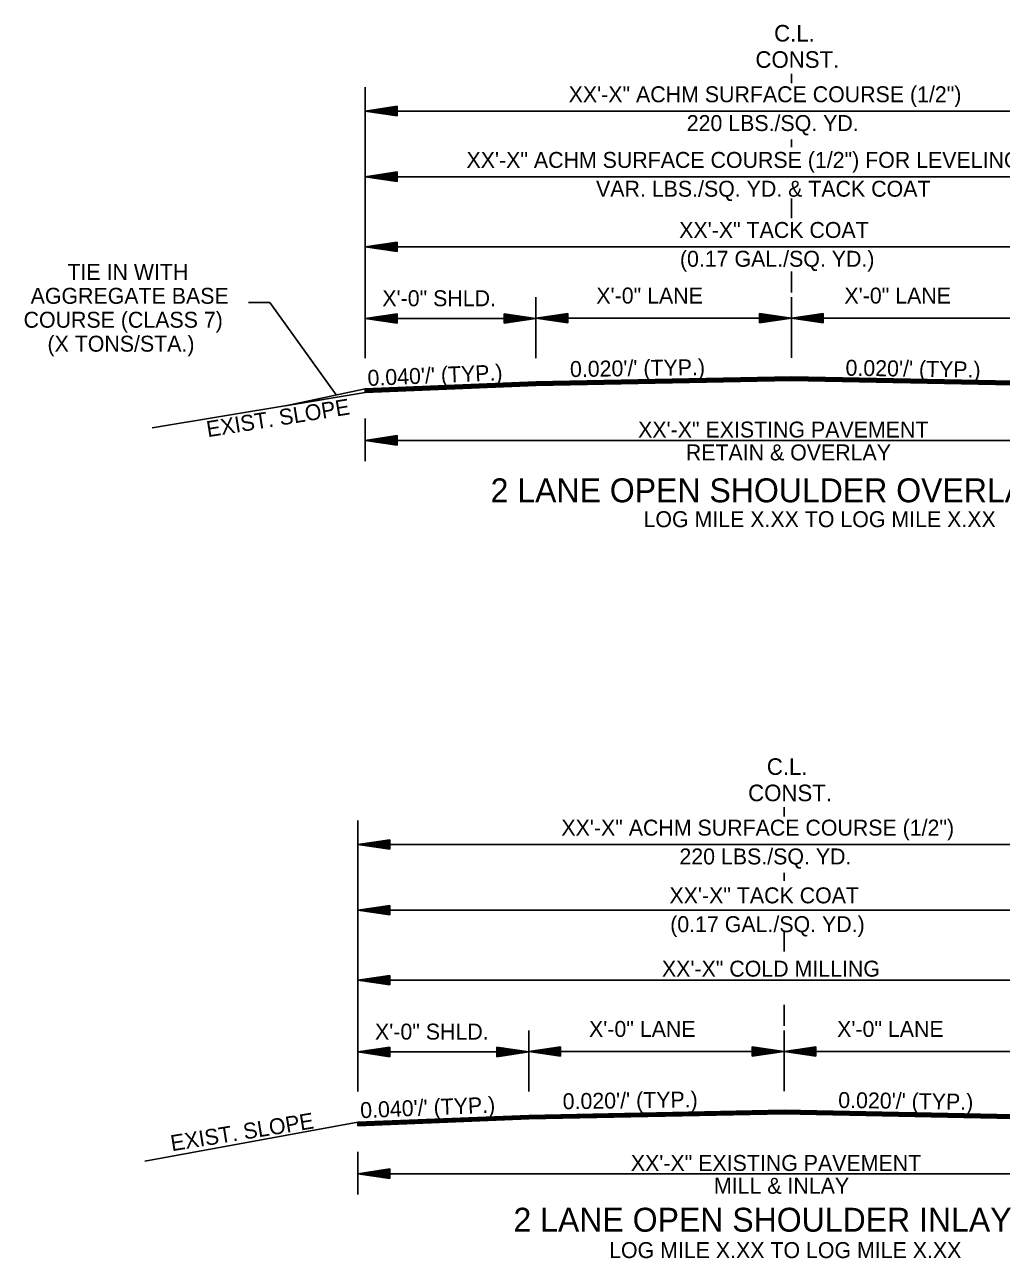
# Model space of a CAD drawing. Extents: x 542112 to 1930787, y -1968972 to 596640.
# Drawn here: x 546620 to 547079, y -1954575 to -1953995 of the extents above; entities that cross this region are included whole.
import ezdxf

# ---------------------------------------------------------------- set-up
doc = ezdxf.new("R2010")
doc.units = 0
doc.layers.add('R_Draft', color=7, linetype='Continuous')

msp = doc.modelspace()

# ---------------------------------------------------------------- linework, layer by layer
at = {"layer": 'R_Draft'}
for p, q in [((546980.34, -1954022.43), (546980.34, -1954018.02)), ((546780.08, -1954024.27), (546780.08, -1954151.7)), ((546795.08, -1954033.28), (546780.08, -1954035.53)), ((546780.08, -1954035.53), (547180.53, -1954035.53)), ((546795.08, -1954037.78), (546780.08, -1954035.53)), ((546795.08, -1954033.66), (546782.59, -1954035.53)), ((546795.08, -1954037.41), (546782.59, -1954035.53)), ((546795.08, -1954034.04), (546785.17, -1954035.53)), ((546795.08, -1954037.03), (546785.17, -1954035.53)), ((546795.08, -1954034.42), (546787.66, -1954035.53)), ((546795.08, -1954036.65), (546787.66, -1954035.53)), ((546795.08, -1954034.8), (546790.21, -1954035.53)), ((546795.08, -1954036.26), (546790.21, -1954035.53)), ((546795.08, -1954035.18), (546792.71, -1954035.53)), ((546795.08, -1954035.89), (546792.71, -1954035.53)), ((546795.08, -1954037.78), (546795.08, -1954033.28)), ((546980.34, -1954052.56), (546980.34, -1954048.89)), ((546795.08, -1954064.15), (546780.08, -1954066.4)), ((546795.08, -1954064.53), (546782.59, -1954066.4)), ((546795.08, -1954064.91), (546785.17, -1954066.4)), ((546795.08, -1954065.29), (546787.66, -1954066.4)), ((546795.08, -1954068.65), (546795.08, -1954064.15)), ((546780.08, -1954066.4), (547180.53, -1954066.4)), ((546795.08, -1954068.65), (546780.08, -1954066.4)), ((546795.08, -1954068.28), (546782.59, -1954066.4)), ((546795.08, -1954067.9), (546785.17, -1954066.4)), ((546795.08, -1954067.52), (546787.66, -1954066.4)), ((546795.08, -1954065.67), (546790.21, -1954066.4)), ((546795.08, -1954067.13), (546790.21, -1954066.4)), ((546795.08, -1954066.05), (546792.71, -1954066.4)), ((546795.08, -1954066.76), (546792.71, -1954066.4)), ((546980.34, -1954085.92), (546980.34, -1954076.62)), ((546795.08, -1954097.08), (546780.08, -1954099.33)), ((546780.08, -1954099.33), (547180.53, -1954099.33)), ((546795.08, -1954101.58), (546780.08, -1954099.33)), ((546795.08, -1954097.46), (546782.59, -1954099.33)), ((546795.08, -1954101.21), (546782.59, -1954099.33)), ((546795.08, -1954097.84), (546785.17, -1954099.33)), ((546795.08, -1954100.83), (546785.17, -1954099.33)), ((546795.08, -1954098.22), (546787.66, -1954099.33)), ((546795.08, -1954100.45), (546787.66, -1954099.33)), ((546795.08, -1954098.6), (546790.21, -1954099.33)), ((546795.08, -1954100.06), (546790.21, -1954099.33)), ((546795.08, -1954098.98), (546792.71, -1954099.33)), ((546795.08, -1954099.69), (546792.71, -1954099.33)), ((546795.08, -1954101.58), (546795.08, -1954097.08)), ((546980.34, -1954120.86), (546980.34, -1954110.99)), ((546860.34, -1954151.53), (546860.34, -1954122.98)), ((546860.34, -1954151.7), (546860.34, -1954122.98)), ((546980.34, -1954151.53), (546980.34, -1954122.98)), ((546795.08, -1954130.79), (546780.08, -1954133.04)), ((546860.34, -1954133.04), (546780.08, -1954133.04)), ((546795.08, -1954135.29), (546780.08, -1954133.04)), ((546795.08, -1954131.17), (546782.59, -1954133.04)), ((546795.08, -1954134.92), (546782.59, -1954133.04)), ((546795.08, -1954131.55), (546785.17, -1954133.04)), ((546795.08, -1954134.53), (546785.17, -1954133.04)), ((546795.08, -1954131.92), (546787.66, -1954133.04)), ((546795.08, -1954134.16), (546787.66, -1954133.04)), ((546795.08, -1954132.31), (546790.21, -1954133.04)), ((546795.08, -1954133.77), (546790.21, -1954133.04)), ((546795.08, -1954132.69), (546792.71, -1954133.04)), ((546795.08, -1954133.39), (546792.71, -1954133.04)), ((546795.08, -1954135.29), (546795.08, -1954130.79)), ((546845.34, -1954130.79), (546860.34, -1954133.04)), ((546845.34, -1954130.79), (546845.34, -1954135.29)), ((546845.34, -1954131.17), (546857.84, -1954133.04)), ((546845.34, -1954131.55), (546855.26, -1954133.04)), ((546845.34, -1954131.92), (546852.76, -1954133.04)), ((546845.34, -1954132.31), (546850.22, -1954133.04)), ((546845.34, -1954132.69), (546847.71, -1954133.04)), ((546845.34, -1954135.29), (546860.34, -1954133.04)), ((546845.34, -1954133.78), (546850.22, -1954133.04)), ((546845.34, -1954134.53), (546855.26, -1954133.04)), ((546845.34, -1954134.92), (546857.84, -1954133.04)), ((546845.34, -1954134.16), (546852.76, -1954133.04)), ((546845.34, -1954133.39), (546847.71, -1954133.04)), ((546875.34, -1954130.62), (546860.34, -1954132.87)), ((546980.34, -1954132.87), (546860.34, -1954132.87)), ((546875.34, -1954135.12), (546860.34, -1954132.87)), ((546875.34, -1954131), (546862.85, -1954132.87)), ((546875.34, -1954134.75), (546862.85, -1954132.87)), ((546875.34, -1954131.38), (546865.43, -1954132.87)), ((546875.34, -1954134.36), (546865.43, -1954132.87)), ((546875.34, -1954131.75), (546867.93, -1954132.87)), ((546875.34, -1954133.99), (546867.93, -1954132.87)), ((546875.34, -1954132.14), (546870.47, -1954132.87)), ((546875.34, -1954133.6), (546870.47, -1954132.87)), ((546875.34, -1954132.52), (546872.97, -1954132.87)), ((546875.34, -1954133.22), (546872.97, -1954132.87)), ((546875.34, -1954135.12), (546875.34, -1954130.62)), ((546965.34, -1954130.62), (546980.34, -1954132.87)), ((546965.34, -1954130.62), (546965.34, -1954135.12)), ((546965.34, -1954131), (546977.84, -1954132.87)), ((546965.34, -1954131.38), (546975.26, -1954132.87)), ((546965.34, -1954131.75), (546972.76, -1954132.87)), ((546965.34, -1954132.14), (546970.22, -1954132.87)), ((546965.34, -1954132.52), (546967.71, -1954132.87)), ((546965.34, -1954135.12), (546980.34, -1954132.87)), ((546965.34, -1954133.61), (546970.22, -1954132.87)), ((546965.34, -1954134.36), (546975.26, -1954132.87)), ((546965.34, -1954134.75), (546977.84, -1954132.87)), ((546965.34, -1954133.99), (546972.76, -1954132.87)), ((546965.34, -1954133.22), (546967.71, -1954132.87)), ((546995.34, -1954130.62), (546980.34, -1954132.87)), ((547100.27, -1954132.87), (546980.34, -1954132.87)), ((546995.34, -1954135.12), (546980.34, -1954132.87)), ((546995.34, -1954131), (546982.85, -1954132.87)), ((546995.34, -1954134.75), (546982.85, -1954132.87)), ((546995.34, -1954131.38), (546985.43, -1954132.87)), ((546995.34, -1954134.36), (546985.43, -1954132.87)), ((546995.34, -1954131.75), (546987.93, -1954132.87)), ((546995.34, -1954133.99), (546987.93, -1954132.87)), ((546995.34, -1954132.14), (546990.47, -1954132.87)), ((546995.34, -1954133.6), (546990.47, -1954132.87)), ((546995.34, -1954132.52), (546992.97, -1954132.87)), ((546995.34, -1954133.22), (546992.97, -1954132.87)), ((546995.34, -1954135.12), (546995.34, -1954130.62)), ((546780.08, -1954166.09), (546860.34, -1954162.88)), ((546780.08, -1954166.39), (546860.36, -1954163.18)), ((546780.08, -1954166.69), (546860.37, -1954163.48)), ((546780.08, -1954166.99), (546860.38, -1954163.78)), ((546780.08, -1954167.29), (546860.39, -1954164.08)), ((546980.34, -1954160.48), (546860.34, -1954162.88)), ((546980.35, -1954160.78), (546860.35, -1954163.18)), ((546980.36, -1954161.08), (546860.36, -1954163.48)), ((546980.36, -1954161.38), (546860.36, -1954163.78)), ((546980.37, -1954161.68), (546860.37, -1954164.08)), ((546980.37, -1954161.98), (546860.37, -1954164.38)), ((546980.38, -1954162.18), (546860.38, -1954164.58)), ((546980.31, -1954161.98), (547100.31, -1954164.38)), ((546980.31, -1954162.18), (547100.31, -1954164.58)), ((546980.32, -1954161.68), (547100.32, -1954164.08)), ((546980.33, -1954161.08), (547100.33, -1954163.48)), ((546980.33, -1954161.38), (547100.33, -1954163.78)), ((546980.34, -1954160.48), (547100.34, -1954162.88)), ((546980.34, -1954160.78), (547100.34, -1954163.18)), ((546780.08, -1954167.79), (546680.01, -1954184.46)), ((546780.08, -1954166.09), (546742.59, -1954174.03)), ((546742.59, -1954174.03), (546780.08, -1954167.79)), ((546780.08, -1954167.59), (546860.4, -1954164.38)), ((546780.08, -1954167.79), (546860.41, -1954164.58)), ((546780.08, -1954167.79), (546780.08, -1954166.09)), ((546780.08, -1954167.79), (546780.08, -1954166.09)), ((546780.08, -1954167.79), (546780.08, -1954166.09)), ((546780.08, -1954167.79), (546780.08, -1954167.79)), ((546780.08, -1954180.09), (546780.08, -1954200.09)), ((546795.08, -1954188.09), (546780.08, -1954190.34)), ((546780.08, -1954190.34), (547180.53, -1954190.34)), ((546795.08, -1954192.59), (546780.08, -1954190.34)), ((546795.08, -1954188.46), (546782.59, -1954190.34)), ((546795.08, -1954192.21), (546782.59, -1954190.34)), ((546795.08, -1954188.84), (546785.17, -1954190.34)), ((546795.08, -1954191.83), (546785.17, -1954190.34)), ((546795.08, -1954189.22), (546787.66, -1954190.34)), ((546795.08, -1954191.45), (546787.66, -1954190.34)), ((546795.08, -1954189.6), (546790.21, -1954190.34)), ((546795.08, -1954191.06), (546790.21, -1954190.34)), ((546795.08, -1954189.98), (546792.71, -1954190.34)), ((546795.08, -1954190.69), (546792.71, -1954190.34)), ((546795.08, -1954192.59), (546795.08, -1954188.09)), ((546976.91, -1954367.23), (546976.91, -1954362.81)), ((546776.65, -1954369.07), (546776.65, -1954496.49)), ((546791.65, -1954378.08), (546776.65, -1954380.33)), ((546791.65, -1954378.45), (546779.16, -1954380.33)), ((546791.65, -1954382.58), (546791.65, -1954378.08)), ((546776.65, -1954380.33), (547177.1, -1954380.33)), ((546791.65, -1954382.58), (546776.65, -1954380.33)), ((546791.65, -1954382.2), (546779.16, -1954380.33)), ((546791.65, -1954378.84), (546781.74, -1954380.33)), ((546791.65, -1954381.82), (546781.74, -1954380.33)), ((546791.65, -1954379.21), (546784.24, -1954380.33)), ((546791.65, -1954381.45), (546784.24, -1954380.33)), ((546791.65, -1954379.59), (546786.78, -1954380.33)), ((546791.65, -1954381.06), (546786.78, -1954380.33)), ((546791.65, -1954379.98), (546789.28, -1954380.33)), ((546791.65, -1954380.68), (546789.28, -1954380.33)), ((546976.91, -1954397.35), (546976.91, -1954393.68)), ((546791.65, -1954408.95), (546776.65, -1954411.2)), ((546776.65, -1954411.2), (547177.1, -1954411.2)), ((546791.65, -1954413.45), (546776.65, -1954411.2)), ((546791.65, -1954409.32), (546779.16, -1954411.2)), ((546791.65, -1954413.07), (546779.16, -1954411.2)), ((546791.65, -1954409.71), (546781.74, -1954411.2)), ((546791.65, -1954412.69), (546781.74, -1954411.2)), ((546791.65, -1954410.08), (546784.24, -1954411.2)), ((546791.65, -1954412.32), (546784.24, -1954411.2)), ((546791.65, -1954410.46), (546786.78, -1954411.2)), ((546791.65, -1954411.93), (546786.78, -1954411.2)), ((546791.65, -1954410.85), (546789.28, -1954411.2)), ((546791.65, -1954411.55), (546789.28, -1954411.2)), ((546791.65, -1954413.45), (546791.65, -1954408.95)), ((546976.91, -1954430.71), (546976.91, -1954421.41)), ((546791.65, -1954441.88), (546776.65, -1954444.13)), ((546791.65, -1954442.25), (546779.16, -1954444.13)), ((546791.65, -1954446.38), (546791.65, -1954441.88)), ((546776.65, -1954444.13), (547177.1, -1954444.13)), ((546791.65, -1954446.38), (546776.65, -1954444.13)), ((546791.65, -1954446), (546779.16, -1954444.13)), ((546791.65, -1954442.63), (546781.74, -1954444.13)), ((546791.65, -1954445.62), (546781.74, -1954444.13)), ((546791.65, -1954443.01), (546784.24, -1954444.13)), ((546791.65, -1954445.24), (546784.24, -1954444.13)), ((546791.65, -1954443.39), (546786.78, -1954444.13)), ((546791.65, -1954444.85), (546786.78, -1954444.13)), ((546791.65, -1954443.77), (546789.28, -1954444.13)), ((546791.65, -1954444.48), (546789.28, -1954444.13)), ((546976.91, -1954465.65), (546976.91, -1954455.78)), ((546856.91, -1954496.32), (546856.91, -1954467.77)), ((546856.91, -1954496.49), (546856.91, -1954467.77)), ((546976.91, -1954496.32), (546976.91, -1954467.77)), ((546791.65, -1954475.58), (546776.65, -1954477.83)), ((546791.65, -1954475.96), (546779.16, -1954477.83)), ((546791.65, -1954476.34), (546781.74, -1954477.83)), ((546791.65, -1954476.72), (546784.24, -1954477.83)), ((546791.65, -1954477.1), (546786.78, -1954477.83)), ((546791.65, -1954480.08), (546791.65, -1954475.58)), ((546841.91, -1954475.58), (546856.91, -1954477.83)), ((546841.91, -1954475.58), (546841.91, -1954480.08)), ((546841.91, -1954475.96), (546854.41, -1954477.83)), ((546841.91, -1954476.34), (546851.83, -1954477.83)), ((546841.91, -1954476.72), (546849.33, -1954477.83)), ((546841.91, -1954477.11), (546846.79, -1954477.83)), ((546871.91, -1954475.41), (546856.91, -1954477.66)), ((546871.91, -1954475.79), (546859.42, -1954477.66)), ((546871.91, -1954476.17), (546862, -1954477.66)), ((546871.91, -1954476.55), (546864.5, -1954477.66)), ((546871.91, -1954476.93), (546867.04, -1954477.66)), ((546871.91, -1954477.31), (546869.54, -1954477.66)), ((546871.91, -1954479.91), (546871.91, -1954475.41)), ((546961.91, -1954475.41), (546976.91, -1954477.66)), ((546961.91, -1954475.41), (546961.91, -1954479.91)), ((546961.91, -1954475.79), (546974.41, -1954477.66)), ((546961.91, -1954476.17), (546971.83, -1954477.66)), ((546961.91, -1954476.55), (546969.33, -1954477.66)), ((546961.91, -1954476.94), (546966.79, -1954477.66)), ((546961.91, -1954477.31), (546964.28, -1954477.66)), ((546991.91, -1954475.41), (546976.91, -1954477.66)), ((546991.91, -1954475.79), (546979.42, -1954477.66)), ((546991.91, -1954476.17), (546982, -1954477.66)), ((546991.91, -1954476.55), (546984.5, -1954477.66)), ((546991.91, -1954476.93), (546987.04, -1954477.66)), ((546991.91, -1954477.31), (546989.54, -1954477.66)), ((546991.91, -1954479.91), (546991.91, -1954475.41)), ((546856.91, -1954477.83), (546776.65, -1954477.83)), ((546791.65, -1954480.08), (546776.65, -1954477.83)), ((546791.65, -1954479.71), (546779.16, -1954477.83)), ((546791.65, -1954479.33), (546781.74, -1954477.83)), ((546791.65, -1954478.95), (546784.24, -1954477.83)), ((546791.65, -1954478.56), (546786.78, -1954477.83)), ((546791.65, -1954477.48), (546789.28, -1954477.83)), ((546791.65, -1954478.19), (546789.28, -1954477.83)), ((546841.91, -1954477.48), (546844.28, -1954477.83)), ((546841.91, -1954480.08), (546856.91, -1954477.83)), ((546841.91, -1954478.57), (546846.79, -1954477.83)), ((546841.91, -1954479.33), (546851.83, -1954477.83)), ((546841.91, -1954479.71), (546854.41, -1954477.83)), ((546841.91, -1954478.95), (546849.33, -1954477.83)), ((546841.91, -1954478.19), (546844.28, -1954477.83)), ((546976.91, -1954477.66), (546856.91, -1954477.66)), ((546871.91, -1954479.91), (546856.91, -1954477.66)), ((546871.91, -1954479.54), (546859.42, -1954477.66)), ((546871.91, -1954479.16), (546862, -1954477.66)), ((546871.91, -1954478.78), (546864.5, -1954477.66)), ((546871.91, -1954478.39), (546867.04, -1954477.66)), ((546871.91, -1954478.02), (546869.54, -1954477.66)), ((546961.91, -1954479.91), (546976.91, -1954477.66)), ((546961.91, -1954478.4), (546966.79, -1954477.66)), ((546961.91, -1954479.16), (546971.83, -1954477.66)), ((546961.91, -1954479.54), (546974.41, -1954477.66)), ((546961.91, -1954478.78), (546969.33, -1954477.66)), ((546961.91, -1954478.02), (546964.28, -1954477.66)), ((547096.84, -1954477.66), (546976.91, -1954477.66)), ((546991.91, -1954479.91), (546976.91, -1954477.66)), ((546991.91, -1954479.54), (546979.42, -1954477.66)), ((546991.91, -1954479.16), (546982, -1954477.66)), ((546991.91, -1954478.78), (546984.5, -1954477.66)), ((546991.91, -1954478.39), (546987.04, -1954477.66)), ((546991.91, -1954478.02), (546989.54, -1954477.66)), ((546976.91, -1954505.27), (546856.91, -1954507.67)), ((546976.92, -1954505.57), (546856.92, -1954507.97)), ((546976.93, -1954505.87), (546856.93, -1954508.27)), ((546976.93, -1954506.17), (546856.93, -1954508.57)), ((546976.9, -1954505.87), (547096.9, -1954508.27)), ((546976.9, -1954506.17), (547096.9, -1954508.57)), ((546976.91, -1954505.27), (547096.91, -1954507.67)), ((546976.91, -1954505.57), (547096.91, -1954507.97)), ((546776.65, -1954510.88), (546676.59, -1954529.26)), ((546776.65, -1954510.88), (546856.91, -1954507.67)), ((546776.65, -1954511.18), (546856.93, -1954507.97)), ((546776.65, -1954511.48), (546856.94, -1954508.27)), ((546776.65, -1954511.78), (546856.95, -1954508.57)), ((546776.65, -1954512.08), (546856.96, -1954508.87)), ((546776.65, -1954512.38), (546856.97, -1954509.17)), ((546776.65, -1954512.58), (546856.98, -1954509.37)), ((546776.65, -1954512.58), (546776.65, -1954510.88)), ((546776.65, -1954512.58), (546776.65, -1954510.88)), ((546776.65, -1954512.58), (546776.65, -1954510.88)), ((546976.94, -1954506.47), (546856.94, -1954508.87)), ((546976.94, -1954506.77), (546856.94, -1954509.17)), ((546976.95, -1954506.97), (546856.95, -1954509.37)), ((546976.88, -1954506.77), (547096.88, -1954509.17)), ((546976.88, -1954506.97), (547096.88, -1954509.37)), ((546976.89, -1954506.47), (547096.89, -1954508.87)), ((546776.65, -1954524.88), (546776.65, -1954544.88)), ((546791.65, -1954532.88), (546776.65, -1954535.13)), ((546776.65, -1954535.13), (547177.1, -1954535.13)), ((546791.65, -1954537.38), (546776.65, -1954535.13)), ((546791.65, -1954533.25), (546779.16, -1954535.13)), ((546791.65, -1954537), (546779.16, -1954535.13)), ((546791.65, -1954533.64), (546781.74, -1954535.13)), ((546791.65, -1954536.62), (546781.74, -1954535.13)), ((546791.65, -1954534.01), (546784.24, -1954535.13)), ((546791.65, -1954536.25), (546784.24, -1954535.13)), ((546791.65, -1954534.39), (546786.78, -1954535.13)), ((546791.65, -1954535.86), (546786.78, -1954535.13)), ((546791.65, -1954534.78), (546789.28, -1954535.13)), ((546791.65, -1954535.48), (546789.28, -1954535.13)), ((546791.65, -1954537.38), (546791.65, -1954532.88))]:
    msp.add_line(p, q, dxfattribs=at)
msp.add_lwpolyline([(546725.23, -1954125.59), (546735.23, -1954125.59), (546766.39, -1954168.99)], dxfattribs=at)

# ---------------------------------------------------------------- texts
for s, height, p in [('C.L.', 7.8, (546972.24, -1954002.82)), ('CONST.', 7.8, (546963.46, -1954015.19)), ('XX\'-X" ACHM SURFACE COURSE (1/2")', 7.5, (546875.69, -1954031.37)), ('220 LBS./SQ. YD. ', 7.5, (546931.17, -1954044.91)), ('XX\'-X" ACHM SURFACE COURSE (1/2") FOR LEVELING *', 7.5, (546827.68, -1954062.24)), ('VAR. LBS./SQ. YD. & TACK COAT', 7.5, (546888.56, -1954075.78)), ('XX\'-X" TACK COAT', 7.5, (546927.63, -1954095.17)), ('(0.17 GAL./SQ. YD.)', 7.5, (546927.98, -1954108.71)), ('TIE IN WITH ', 7.5, (546640.15, -1954114.88)), ('AGGREGATE BASE', 7.5, (546622.85, -1954126.13)), ('X\'-0" SHLD.', 7.5, (546788.12, -1954127.27)), ('X\'-0" LANE', 7.5, (546888.69, -1954126.01)), ('X\'-0" LANE', 7.5, (547005.28, -1954126.01)), ('COURSE (CLASS 7)', 7.5, (546619.54, -1954137.38)), ('(X TONS/STA.)', 7.5, (546630.76, -1954148.63)), ('XX\'-X" EXISTING PAVEMENT', 7.5, (546908.32, -1954189.01)), ('RETAIN & OVERLAY', 7.5, (546930.74, -1954199.74)), ('2 LANE OPEN SHOULDER OVERLAY', 11.25, (546839.01, -1954219.45)), ('LOG MILE X.XX TO LOG MILE X.XX', 7.5, (546910.87, -1954231.14)), ('C.L.', 7.8, (546968.81, -1954347.61)), ('CONST.', 7.8, (546960.03, -1954359.98)), ('XX\'-X" ACHM SURFACE COURSE (1/2")', 7.5, (546872.26, -1954376.16)), ('220 LBS./SQ. YD. ', 7.5, (546927.74, -1954389.7)), ('XX\'-X" TACK COAT', 7.5, (546923.06, -1954407.99)), ('(0.17 GAL./SQ. YD.)', 7.5, (546923.41, -1954421.54)), ('XX\'-X" COLD MILLING', 7.5, (546919.52, -1954442.46)), ('X\'-0" SHLD.', 7.5, (546784.69, -1954472.06)), ('X\'-0" LANE', 7.5, (546885.26, -1954470.8)), ('X\'-0" LANE', 7.5, (547001.85, -1954470.8)), ('XX\'-X" EXISTING PAVEMENT', 7.5, (546904.9, -1954533.81)), ('MILL & INLAY', 7.5, (546943.96, -1954544.53)), ('2 LANE OPEN SHOULDER INLAY', 11.25, (546849.75, -1954562.37)), ('LOG MILE X.XX TO LOG MILE X.XX', 7.5, (546894.71, -1954574.78))]:
    msp.add_text(s, height=height, dxfattribs=at).set_placement(p)
for s, rotation, p in [("0.020'/' (TYP.)", 0.87191, (546876.36, -1954160.58)), ("0.020'/' (TYP.)", 359.16404, (547005.76, -1954159.92)), ("0.040'/' (TYP.)", 2.44797, (546781.32, -1954164.77)), ('EXIST. SLOPE', 9.15344, (546706.1, -1954188.87)), ("0.040'/' (TYP.)", 2.44797, (546777.89, -1954509.03)), ("0.020'/' (TYP.)", 0.87191, (546872.93, -1954504.83)), ("0.020'/' (TYP.)", 359.16404, (547002.33, -1954504.18)), ('EXIST. SLOPE', 9.15344, (546689.24, -1954524.55))]:
    msp.add_text(s, height=7.5, rotation=rotation, dxfattribs=at).set_placement(p)

doc.saveas('drawing.dxf')
